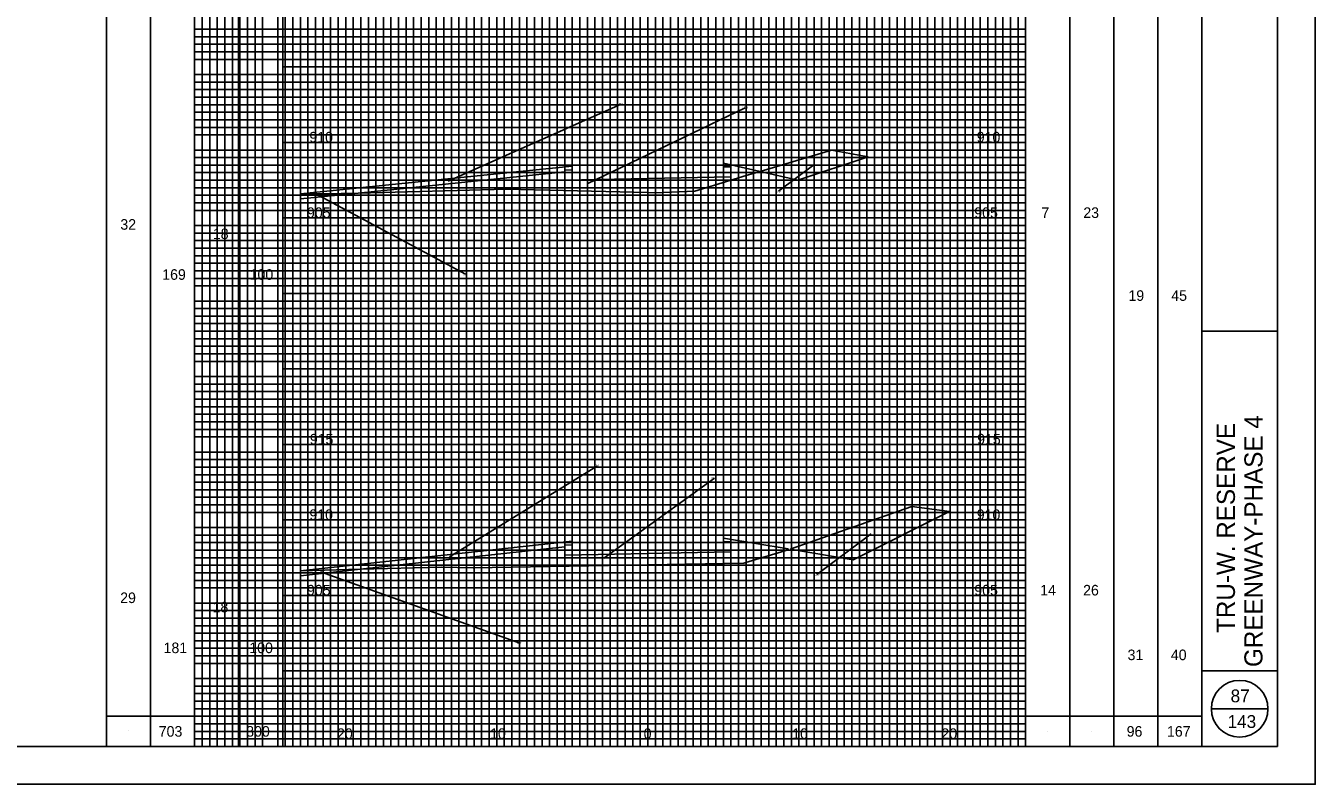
# Model space of a CAD drawing. Extents: x -73 to 160, y -2 to 1877.
# Drawn here: x 74.7 to 160, y 1492.5 to 1542.7 of the extents above; entities that cross this region are included whole.
import ezdxf

# ---------------------------------------------------------------- set-up
doc = ezdxf.new("R2010")
doc.units = 0
for name, color, linetype in [('DR_P_Flood_Boundary', 7, 'Continuous'), ('GK_Cells', 7, 'Continuous'), ('RD_X_Fence', 7, 'Continuous'), ('TX_X_5', 7, 'Continuous'), ('UT_P_Water_Cells', 7, 'Continuous'), ('XS_P_Pavt_Layers', 7, 'Continuous'), ('XS_P_Pavt_Surface', 7, 'Continuous'), ('XS_X_Ground_Line', 7, 'Continuous')]:
    doc.layers.add(name, color=color, linetype=linetype)

msp = doc.modelspace()

# ---------------------------------------------------------------- linework, layer by layer
at = {"layer": 'DR_P_Flood_Boundary'}
for p, q in [((95.832, 1495), (95.832, 1600)), ((100.832, 1495), (100.832, 1600)), ((105.832, 1495), (105.832, 1600)), ((110.832, 1495), (110.832, 1600)), ((115.832, 1495), (115.832, 1600)), ((120.832, 1495), (120.832, 1600)), ((125.832, 1495), (125.832, 1600)), ((130.832, 1495), (130.832, 1600)), ((135.832, 1495), (135.832, 1600)), ((91.665, 1540), (140.832, 1540)), ((91.665, 1535), (140.832, 1535)), ((91.665, 1530), (140.832, 1530)), ((91.665, 1525), (140.832, 1525)), ((91.665, 1520), (140.832, 1520)), ((91.665, 1515), (140.832, 1515)), ((91.665, 1510), (140.832, 1510)), ((91.665, 1505), (140.832, 1505)), ((91.665, 1500), (140.832, 1500))]:
    msp.add_line(p, q, dxfattribs=at)
at = {"layer": 'GK_Cells'}
for p, q in [((152.5, 1495), (152.5, 1600)), ((152.5, 1522.5), (157.5, 1522.5)), ((152.5, 1500), (157.5, 1500))]:
    msp.add_line(p, q, dxfattribs=at)
msp.add_lwpolyline([(0, 1600), (157.5, 1600), (157.5, 1495), (0, 1495)], close=True, dxfattribs=at)
at = {"layer": 'RD_X_Fence'}
for p, q in [((102.608, 1532.434), (114.072, 1537.537)), ((111.81, 1532.264), (122.265, 1537.299)), ((123.256, 1533.076), (120.832, 1533.636)), ((125.752, 1532.5), (130.421, 1534.047)), ((110.832, 1533.436), (92.832, 1531.588)), ((110.332, 1533.055), (96.651, 1531.65)), ((96.651, 1531.65), (110.332, 1533.055)), ((110.332, 1533.176), (110.832, 1533.186)), ((110.332, 1533.055), (110.332, 1533.176)), ((110.332, 1532.509), (110.332, 1533.055)), ((121.332, 1532.729), (110.332, 1532.509)), ((110.832, 1533.332), (110.832, 1533.436)), ((110.832, 1533.186), (110.832, 1533.332)), ((120.832, 1533.386), (121.332, 1533.396)), ((121.252, 1532.481), (122.332, 1532.802)), ((121.332, 1533.396), (121.332, 1532.729)), ((122.332, 1532.802), (123.256, 1533.076)), ((123.256, 1533.076), (125.752, 1532.5)), ((126.816, 1533.509), (124.487, 1531.766)), ((92.832, 1531.258), (96.651, 1531.65)), ((94.386, 1531.59), (92.832, 1531.588)), ((92.832, 1531.588), (94.066, 1531.59)), ((92.832, 1531.588), (92.832, 1531.258)), ((94.066, 1531.59), (94.386, 1531.59)), ((94.066, 1531.491), (103.771, 1526.276)), ((96.651, 1531.65), (94.386, 1531.59)), ((94.386, 1531.59), (96.651, 1531.65)), ((102.712, 1507.558), (112.505, 1513.585)), ((112.92, 1507.461), (120.24, 1512.777)), ((129.419, 1507.37), (135.788, 1510.554)), ((125.122, 1508.086), (120.832, 1508.801)), ((130.609, 1509.078), (127.013, 1506.383)), ((110.832, 1508.601), (92.832, 1506.637)), ((110.332, 1508.217), (96.822, 1506.742)), ((96.822, 1506.742), (110.332, 1508.217)), ((110.332, 1508.341), (110.832, 1508.351)), ((110.332, 1508.217), (110.332, 1508.341)), ((110.332, 1507.674), (110.332, 1508.217)), ((110.832, 1508.497), (110.832, 1508.601)), ((110.832, 1508.351), (110.832, 1508.497)), ((120.832, 1508.551), (121.332, 1508.561)), ((121.332, 1508.561), (121.332, 1507.894)), ((125.247, 1508.065), (129.419, 1507.37)), ((121.332, 1507.894), (110.332, 1507.674)), ((115.832, 1507.036), (122.178, 1507.147)), ((92.832, 1506.637), (96.822, 1506.742)), ((92.832, 1506.307), (96.822, 1506.742)), ((96.822, 1506.742), (92.832, 1506.637)), ((92.832, 1506.637), (92.832, 1506.307)), ((94.162, 1506.562), (107.363, 1501.848)), ((109.332, 1506.921), (115.832, 1507.036))]:
    msp.add_line(p, q, dxfattribs=at)
for points in [[(130.421, 1534.047), (127.99, 1534.483), (123.256, 1533.076)], [(120.832, 1533.636), (120.832, 1533.532), (120.832, 1533.386)], [(96.651, 1531.65), (106.475, 1531.91), (109.332, 1531.84)], [(109.332, 1531.84), (115.832, 1531.682), (116.357, 1531.669)], [(116.357, 1531.669), (118.948, 1531.783), (121.252, 1532.481)], [(135.788, 1510.554), (133.305, 1510.887), (125.247, 1508.065)], [(120.832, 1508.801), (120.832, 1508.697), (120.832, 1508.551)], [(122.178, 1507.147), (122.321, 1507.19), (125.11, 1508.018)], [(125.11, 1508.018), (125.122, 1508.086)], [(96.822, 1506.742), (102.175, 1506.883), (104.275, 1506.832), (109.332, 1506.921)]]:
    msp.add_lwpolyline(points, dxfattribs=at)
at = {"layer": 'TX_X_5'}
msp.add_lwpolyline([(-10, 1492.5), (160, 1492.5), (160, 1602.5), (-10, 1602.5)], close=True, dxfattribs=at)
at = {"layer": 'UT_P_Water_Cells'}
for p, q in [((86.332, 1495), (86.332, 1600)), ((86.832, 1495), (86.832, 1600)), ((87.332, 1495), (87.332, 1600)), ((87.832, 1495), (87.832, 1600)), ((88.332, 1495), (88.332, 1600)), ((88.832, 1495), (88.832, 1600)), ((89.332, 1495), (89.332, 1600)), ((89.832, 1495), (89.832, 1600)), ((90.332, 1495), (90.332, 1600)), ((91.332, 1495), (91.332, 1600)), ((91.832, 1495), (91.832, 1600)), ((92.332, 1495), (92.332, 1600)), ((92.832, 1495), (92.832, 1600)), ((93.332, 1495), (93.332, 1600)), ((93.832, 1495), (93.832, 1600)), ((94.332, 1495), (94.332, 1600)), ((94.832, 1495), (94.832, 1600)), ((95.332, 1495), (95.332, 1600)), ((96.332, 1495), (96.332, 1600)), ((96.832, 1495), (96.832, 1600)), ((97.332, 1495), (97.332, 1600)), ((97.832, 1495), (97.832, 1600)), ((98.332, 1495), (98.332, 1600)), ((98.832, 1495), (98.832, 1600)), ((99.332, 1495), (99.332, 1600)), ((99.832, 1495), (99.832, 1600)), ((100.332, 1495), (100.332, 1600)), ((101.332, 1495), (101.332, 1600)), ((101.832, 1495), (101.832, 1600)), ((102.332, 1495), (102.332, 1600)), ((102.832, 1495), (102.832, 1600)), ((103.332, 1495), (103.332, 1600)), ((103.832, 1495), (103.832, 1600)), ((104.332, 1495), (104.332, 1600)), ((104.832, 1495), (104.832, 1600)), ((105.332, 1495), (105.332, 1600)), ((106.332, 1495), (106.332, 1600)), ((106.832, 1495), (106.832, 1600)), ((107.332, 1495), (107.332, 1600)), ((107.832, 1495), (107.832, 1600)), ((108.332, 1495), (108.332, 1600)), ((108.832, 1495), (108.832, 1600)), ((109.332, 1495), (109.332, 1600)), ((109.832, 1495), (109.832, 1600)), ((110.332, 1495), (110.332, 1600)), ((111.332, 1495), (111.332, 1600)), ((111.832, 1495), (111.832, 1600)), ((112.332, 1495), (112.332, 1600)), ((112.832, 1495), (112.832, 1600)), ((113.332, 1495), (113.332, 1600)), ((113.832, 1495), (113.832, 1600)), ((114.332, 1495), (114.332, 1600)), ((114.832, 1495), (114.832, 1600)), ((115.332, 1495), (115.332, 1600)), ((116.332, 1495), (116.332, 1600)), ((116.832, 1495), (116.832, 1600)), ((117.332, 1495), (117.332, 1600)), ((117.832, 1495), (117.832, 1600)), ((118.332, 1495), (118.332, 1600)), ((118.832, 1495), (118.832, 1600)), ((119.332, 1495), (119.332, 1600)), ((119.832, 1495), (119.832, 1600)), ((120.332, 1495), (120.332, 1600)), ((121.332, 1495), (121.332, 1600)), ((121.832, 1495), (121.832, 1600)), ((122.332, 1495), (122.332, 1600)), ((122.832, 1495), (122.832, 1600)), ((123.332, 1495), (123.332, 1600)), ((123.832, 1495), (123.832, 1600)), ((124.332, 1495), (124.332, 1600)), ((124.832, 1495), (124.832, 1600)), ((125.332, 1495), (125.332, 1600)), ((126.332, 1495), (126.332, 1600)), ((126.832, 1495), (126.832, 1600)), ((127.332, 1495), (127.332, 1600)), ((127.832, 1495), (127.832, 1600)), ((128.332, 1495), (128.332, 1600)), ((128.832, 1495), (128.832, 1600)), ((129.332, 1495), (129.332, 1600)), ((129.832, 1495), (129.832, 1600)), ((130.332, 1495), (130.332, 1600)), ((131.332, 1495), (131.332, 1600)), ((131.832, 1495), (131.832, 1600)), ((132.332, 1495), (132.332, 1600)), ((132.832, 1495), (132.832, 1600)), ((133.332, 1495), (133.332, 1600)), ((133.832, 1495), (133.832, 1600)), ((134.332, 1495), (134.332, 1600)), ((134.832, 1495), (134.832, 1600)), ((135.332, 1495), (135.332, 1600)), ((136.332, 1495), (136.332, 1600)), ((136.832, 1495), (136.832, 1600)), ((137.332, 1495), (137.332, 1600)), ((137.832, 1495), (137.832, 1600)), ((138.332, 1495), (138.332, 1600)), ((138.832, 1495), (138.832, 1600)), ((139.332, 1495), (139.332, 1600)), ((139.832, 1495), (139.832, 1600)), ((140.332, 1495), (140.332, 1600)), ((85.832, 1542.5), (140.832, 1542.5)), ((85.832, 1542), (140.832, 1542)), ((85.832, 1541.5), (140.832, 1541.5)), ((85.832, 1541), (140.832, 1541)), ((85.832, 1540.5), (140.832, 1540.5)), ((85.832, 1539.5), (140.832, 1539.5)), ((85.832, 1539), (140.832, 1539)), ((85.832, 1538.5), (140.832, 1538.5)), ((85.832, 1538), (140.832, 1538)), ((85.832, 1537.5), (140.832, 1537.5)), ((85.832, 1537), (140.832, 1537)), ((85.832, 1536.5), (140.832, 1536.5)), ((85.832, 1536), (140.832, 1536)), ((85.832, 1535.5), (140.832, 1535.5)), ((85.832, 1534.5), (140.832, 1534.5)), ((85.832, 1534), (140.832, 1534)), ((85.832, 1533.5), (140.832, 1533.5)), ((85.832, 1533), (140.832, 1533)), ((85.832, 1532.5), (140.832, 1532.5)), ((85.832, 1532), (140.832, 1532)), ((85.832, 1531.5), (140.832, 1531.5)), ((85.832, 1531), (140.832, 1531)), ((85.832, 1530.5), (140.832, 1530.5)), ((85.832, 1529.5), (140.832, 1529.5)), ((85.832, 1529), (140.832, 1529)), ((85.832, 1528.5), (140.832, 1528.5)), ((85.832, 1528), (140.832, 1528)), ((85.832, 1527.5), (140.832, 1527.5)), ((85.832, 1527), (140.832, 1527)), ((85.832, 1526.5), (140.832, 1526.5)), ((85.832, 1526), (140.832, 1526)), ((85.832, 1525.5), (140.832, 1525.5)), ((85.832, 1524.5), (140.832, 1524.5)), ((85.832, 1524), (140.832, 1524)), ((85.832, 1523.5), (140.832, 1523.5)), ((85.832, 1523), (140.832, 1523)), ((85.832, 1522.5), (140.832, 1522.5)), ((85.832, 1522), (140.832, 1522)), ((85.832, 1521.5), (140.832, 1521.5)), ((85.832, 1521), (140.832, 1521)), ((85.832, 1520.5), (140.832, 1520.5)), ((85.832, 1519.5), (140.832, 1519.5)), ((85.832, 1519), (140.832, 1519)), ((85.832, 1518.5), (140.832, 1518.5)), ((85.832, 1518), (140.832, 1518)), ((85.832, 1517.5), (140.832, 1517.5)), ((85.832, 1517), (140.832, 1517)), ((85.832, 1516.5), (140.832, 1516.5)), ((85.832, 1516), (140.832, 1516)), ((85.832, 1515.5), (140.832, 1515.5)), ((85.832, 1514.5), (140.832, 1514.5)), ((85.832, 1514), (140.832, 1514)), ((85.832, 1513.5), (140.832, 1513.5)), ((85.832, 1513), (140.832, 1513)), ((85.832, 1512.5), (140.832, 1512.5)), ((85.832, 1512), (140.832, 1512)), ((85.832, 1511.5), (140.832, 1511.5)), ((85.832, 1511), (140.832, 1511)), ((85.832, 1510.5), (140.832, 1510.5)), ((85.832, 1509.5), (140.832, 1509.5)), ((85.832, 1509), (140.832, 1509)), ((85.832, 1508.5), (140.832, 1508.5)), ((85.832, 1508), (140.832, 1508)), ((85.832, 1507.5), (140.832, 1507.5)), ((85.832, 1507), (140.832, 1507)), ((85.832, 1506.5), (140.832, 1506.5)), ((85.832, 1506), (140.832, 1506)), ((85.832, 1505.5), (140.832, 1505.5)), ((85.832, 1504.5), (140.832, 1504.5)), ((85.832, 1504), (140.832, 1504)), ((85.832, 1503.5), (140.832, 1503.5)), ((85.832, 1503), (140.832, 1503)), ((85.832, 1502.5), (140.832, 1502.5)), ((85.832, 1502), (140.832, 1502)), ((85.832, 1501.5), (140.832, 1501.5)), ((85.832, 1501), (140.832, 1501)), ((85.832, 1500.5), (140.832, 1500.5)), ((85.832, 1499.5), (140.832, 1499.5)), ((85.832, 1499), (140.832, 1499)), ((85.832, 1498.5), (140.832, 1498.5)), ((85.832, 1498), (140.832, 1498)), ((85.832, 1497.5), (140.832, 1497.5)), ((85.832, 1497), (140.832, 1497)), ((85.832, 1496.5), (140.832, 1496.5)), ((85.832, 1496), (140.832, 1496)), ((85.832, 1495.5), (140.832, 1495.5))]:
    msp.add_line(p, q, dxfattribs=at)
at = {"layer": 'XS_X_Ground_Line'}
for p, q in [((80, 1495), (80, 1600)), ((85.832, 1495), (85.832, 1600)), ((85.832, 1495), (85.832, 1600)), ((91.665, 1495), (91.665, 1600)), ((140.832, 1495), (140.832, 1600)), ((146.667, 1495), (146.667, 1600)), ((82.916, 1495), (82.916, 1598.75)), ((143.75, 1495), (143.75, 1598.75)), ((149.583, 1495), (149.583, 1598.75)), ((88.749, 1495), (88.749, 1596.667)), ((155, 1511.458), (155, 1511.458)), ((155, 1497.925), (155, 1497.925)), ((80, 1497), (91.665, 1497)), ((140.832, 1497), (152.5, 1497)), ((153.125, 1497.5), (156.875, 1497.5)), ((81.458, 1496.03), (81.458, 1496.03)), ((84.374, 1496.03), (84.374, 1496.03)), ((142.291, 1496), (142.291, 1496)), ((145.209, 1496), (145.209, 1496)), ((148.125, 1496), (148.125, 1496)), ((151.042, 1496), (151.042, 1496)), ((155, 1496.225), (155, 1496.225))]:
    msp.add_line(p, q, dxfattribs=at)
msp.add_circle((155, 1497.5), 1.875, dxfattribs=at)

# ---------------------------------------------------------------- texts
at = {"layer": 'RD_X_Fence'}
for s, p in [('5.3', (113.912, 1537.467)), ('17.3', (122.073, 1537.229)), ('6.0', (124.334, 1531.696)), ('0.6', (103.604, 1526.206)), ('5.2', (112.347, 1513.515)), ('20.3', (120.014, 1512.707)), ('13.7', (126.832, 1506.313)), ('0.7', (107.194, 1501.778))]:
    msp.add_text(s, height=0.14, dxfattribs=at).set_placement(p)
at = {"layer": 'XS_P_Pavt_Layers'}
for s, p in [('87', (154.401, 1497.925)), ('143', (154.197, 1496.225))]:
    msp.add_text(s, height=0.85, dxfattribs=at).set_placement(p)
at = {"layer": 'XS_P_Pavt_Surface'}
for s, p in [('910', (93.43, 1535)), ('910', (137.598, 1535)), ('905', (93.27, 1530)), ('905', (137.438, 1530)), ('7', (141.878, 1530)), ('23', (144.653, 1530)), ('32', (80.918, 1529.221)), ('18', (87.041, 1528.602)), ('169', (83.691, 1525.904)), ('100', (89.476, 1525.904)), ('19', (147.639, 1524.511)), ('45', (150.472, 1524.511)), ('915', (93.458, 1515)), ('915', (137.625, 1515)), ('910', (93.43, 1510)), ('910', (137.598, 1510)), ('905', (93.27, 1505)), ('905', (137.438, 1505)), ('14', (141.798, 1505)), ('26', (144.639, 1505)), ('29', (80.907, 1504.498)), ('18', (87.021, 1503.879)), ('181', (83.781, 1501.181)), ('100', (89.454, 1501.181)), ('31', (147.581, 1500.717)), ('40', (150.445, 1500.717)), ('703', (83.46, 1495.65)), ('300', (89.249, 1495.65)), ('20', (95.257, 1495.5)), ('10', (105.389, 1495.5)), ('0', (115.554, 1495.5)), ('0', (115.554, 1495.5)), ('10', (125.389, 1495.5)), ('20', (135.257, 1495.5)), ('96', (147.522, 1495.65)), ('167', (150.19, 1495.65))]:
    msp.add_text(s, height=0.7, dxfattribs=at).set_placement(p)
for s, p in [('GREENWAY-PHASE 4', (156.512, 1500.261)), ('TRU-W. RESERVE', (154.688, 1502.519))]:
    msp.add_text(s, height=1.2, rotation=90, dxfattribs=at).set_placement(p)
at = {"layer": 'XS_X_Ground_Line'}
msp.add_text('143', height=0.85, dxfattribs=at).set_placement((154.197, 1496.225))

doc.saveas('drawing.dxf')
